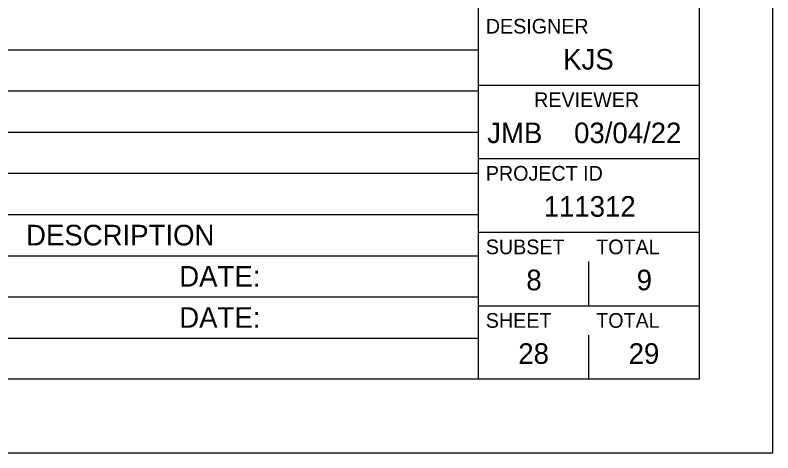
# Model space of a CAD drawing. Extents: x 0 to 128, y -9 to 33.
# Drawn here: x 28.85 to 34, y 0 to 2.98 of the extents above; entities that cross this region are included whole.
import ezdxf

# ---------------------------------------------------------------- set-up
doc = ezdxf.new("R2010")
doc.units = 0
for name, color, linetype in [('Default', 7, 'Continuous'), ('GE_X_Alignment', 7, 'Continuous'), ('GE_X_Alignment_100_Curve_Data', 7, 'Continuous'), ('GE_X_Alignment_100_Stations', 7, 'Continuous'), ('GE_X_Alignment_500_Curve_Data', 7, 'Continuous')]:
    doc.layers.add(name, color=color, linetype=linetype)

msp = doc.modelspace()

# ---------------------------------------------------------------- linework, layer by layer
at = {"layer": 'GE_X_Alignment'}
msp.add_lwpolyline([(0, 0), (34, 0), (34, 22), (0, 22)], close=True, dxfattribs=at)
at = {"layer": 'GE_X_Alignment_100_Curve_Data'}
for p, q in [((32.75, 1), (32.75, 1.3)), ((32.75, 0.5), (32.75, 0.8)), ((32.375, 0.675), (32.375, 0.675))]:
    msp.add_line(p, q, dxfattribs=at)
at = {"layer": 'GE_X_Alignment_100_Stations'}
for p, q in [((32, 0.5), (32, 21.5)), ((32, 2.5), (33.5, 2.5)), ((32, 2), (33.5, 2)), ((32, 1.5), (33.5, 1.5)), ((32, 1), (33.5, 1))]:
    msp.add_line(p, q, dxfattribs=at)
msp.add_lwpolyline([(1.5, 21.5), (33.5, 21.5), (33.5, 0.5), (1.5, 0.5)], close=True, dxfattribs=at)
at = {"layer": 'GE_X_Alignment_500_Curve_Data'}
for p, q in [((25.1966, 2.74), (32, 2.74)), ((25.1966, 2.46), (32, 2.46)), ((25.1966, 2.18), (32, 2.18)), ((25.1966, 1.9), (32, 1.9)), ((25.1966, 1.62), (32, 1.62)), ((25.1966, 1.34), (32, 1.34)), ((25.1966, 1.06), (32, 1.06)), ((25.1966, 0.78), (32, 0.78)), ((32, 0.5), (32, 0.5))]:
    msp.add_line(p, q, dxfattribs=at)

# ---------------------------------------------------------------- texts
at = {"layer": 'Default'}
for s, height, p in [('KJS', 0.14, (32.5757, 2.605)), ('REVIEWER', 0.1, (32.3783, 2.35)), ('JMB', 0.14, (32.0596, 2.105)), ('03/04/22', 0.14, (32.6497, 2.105)), ('111312', 0.14, (32.4435, 1.605)), ('8', 0.14, (32.325, 1.105)), ('9', 0.14, (33.075, 1.105)), ('28', 0.14, (32.2706, 0.605)), ('29', 0.14, (33.0206, 0.605))]:
    msp.add_text(s, height=height, dxfattribs=at).set_placement(p)
at = {"layer": 'GE_X_Alignment_100_Curve_Data'}
for s, p in [('DESIGNER', (32.05, 2.85)), ('PROJECT ID', (32.05, 1.85)), ('SUBSET', (32.05, 1.35)), ('TOTAL', (32.8, 1.35)), ('SHEET', (32.05, 0.85)), ('TOTAL', (32.8, 0.85))]:
    msp.add_text(s, height=0.1, dxfattribs=at).set_placement(p)
at = {"layer": 'GE_X_Alignment_500_Curve_Data'}
for s, p in [('DESCRIPTION', (28.9268, 1.41)), ('DATE:', (29.9673, 1.13)), ('DATE:', (29.9673, 0.85))]:
    msp.add_text(s, height=0.14, dxfattribs=at).set_placement(p)

doc.saveas('drawing.dxf')
